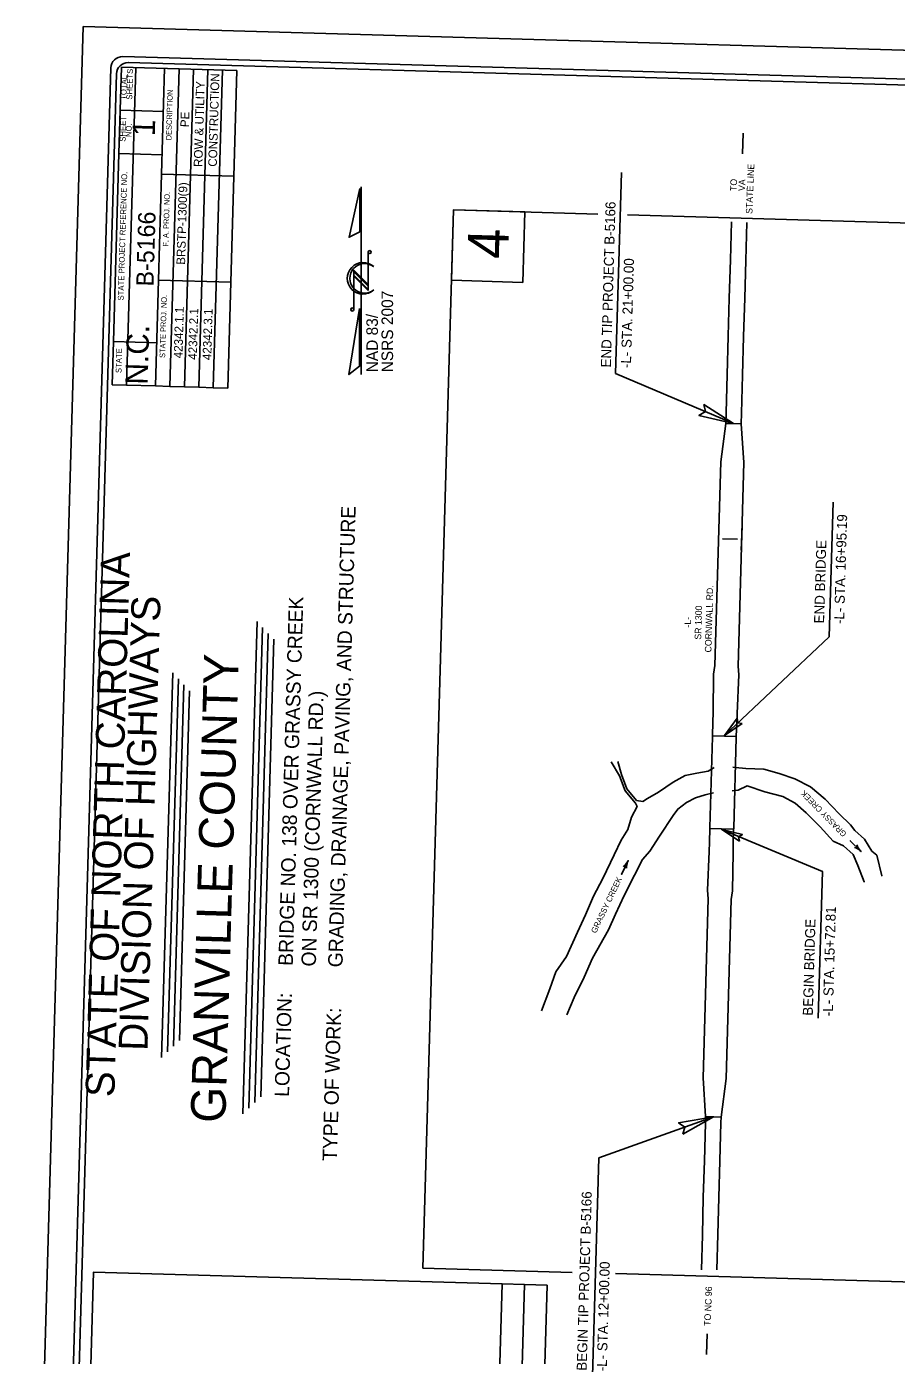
# Model space of a CAD drawing. Extents: x 2097846 to 2099709, y 989477 to 992073.
# Drawn here: x 2097846 to 2098974, y 990349 to 992073 of the extents above; entities that cross this region are included whole.
import ezdxf

# ---------------------------------------------------------------- set-up
doc = ezdxf.new("R2010")
doc.units = 0
for name, color, linetype in [('Exist Hydro Jurisdictional Stream or Body of Water', 7, 'Continuous'), ('Exist Hydro Jurisdictional Stream or Body of Water Text', 7, 'Continuous'), ('Exist Hydro River Flow Arrow CELL', 7, 'Continuous'), ('Exist Roads EOP', 7, 'Continuous'), ('Exist Roads EOP Leader', 7, 'Continuous'), ('Exist Roads EOP Text', 7, 'Continuous'), ('Prop Horizontal Alignment Station Label', 7, 'Continuous'), ('Prop Paved Shoulder', 7, 'Continuous'), ('Prop Shade Light', 7, 'Continuous'), ('Prop Terminator CELL', 7, 'Continuous'), ('Sheet Data Field CELL', 7, 'Continuous'), ('Sheet North Arrow CELL', 7, 'Continuous'), ('Sheet Title CELL', 7, 'Continuous'), ('Stewart Plot Border Xerox6279 and LJ5000', 7, 'Continuous')]:
    doc.layers.add(name, color=color, linetype=linetype)

msp = doc.modelspace()

# ---------------------------------------------------------------- linework, layer by layer
at = {"layer": 'Exist Hydro Jurisdictional Stream or Body of Water'}
for p, q in [((2098920.4, 991029.9), (2098914.8, 991037.2)), ((2098918.2, 990999), (2098905.9, 991010))]:
    msp.add_line(p, q, dxfattribs=at)
for points in [[(2098604.1, 991119.2), (2098615.1, 991100.8), (2098622.6, 991081.7), (2098635.8, 991065.7), (2098638, 991061.1), (2098630.7, 991047.5)], [(2098612.8, 991119.5), (2098617.5, 991102.7), (2098624.7, 991084.1), (2098637.2, 991069), (2098645.5, 991067.5), (2098651.3, 991071.4)], [(2098651.3, 991071.4), (2098665.8, 991080), (2098684.9, 991092.6), (2098700.2, 991101.3), (2098715.5, 991104.5), (2098730.1, 991107), (2098736.7, 991110.9), (2098738, 991111.9)], [(2098762.1, 991112.2), (2098765.7, 991111.8), (2098779.1, 991110.3), (2098802.3, 991109.6), (2098822.4, 991104.1), (2098842.5, 991097.2), (2098863, 991086.9), (2098882, 991070.7), (2098900.2, 991051.9), (2098914.8, 991037.2)], [(2098761.2, 991081.7), (2098768.9, 991082.4), (2098780.7, 991088.1), (2098803.9, 991080.3)], [(2098803.9, 991080.3), (2098827, 991074.2), (2098843.1, 991065.4), (2098857.2, 991052.8), (2098875.6, 991035), (2098892.2, 991016.3), (2098905.9, 991010)], [(2098546.7, 990790.9), (2098556.3, 990813.5), (2098569.3, 990839.8), (2098580.1, 990864.6), (2098601, 990901), (2098609.9, 990921.7), (2098621, 990945.5), (2098634.4, 990972), (2098645, 990992.5), (2098654.4, 991003.4), (2098667, 991022.8), (2098684.8, 991049.6), (2098690.6, 991057.9), (2098702.1, 991066.4), (2098713.9, 991072.4), (2098726.4, 991076.3), (2098737.1, 991078.9)], [(2098513.7, 990795.9), (2098524.7, 990824.8), (2098532.4, 990846.7), (2098546.5, 990866.6), (2098560.8, 990898), (2098571.1, 990920.8), (2098581.3, 990944.9), (2098593.4, 990967.7), (2098608.4, 990998.5), (2098617.1, 991017.4), (2098625.9, 991031.5), (2098630.7, 991047.5)], [(2098920.4, 991029.9), (2098932.9, 991018.7), (2098942.6, 991003.4), (2098949.1, 990997.9), (2098955.7, 990971.1)], [(2098918.2, 990999), (2098924.3, 990984.8), (2098932.8, 990963.5)], [(2098932.8, 990963.5), (2098932.9, 990962.8)], [(2098955.7, 990971.1), (2098955.8, 990970.9)]]:
    msp.add_lwpolyline(points, dxfattribs=at)
at = {"layer": 'Exist Hydro River Flow Arrow CELL'}
for p, q in [((2098921.6, 991009.8), (2098921.6, 991009.8)), ((2098622.2, 990982.1), (2098622.2, 990982.1))]:
    msp.add_line(p, q, dxfattribs=at)
for points in [[(2098923.2, 991011.4), (2098924, 991009.5), (2098924.9, 991007.7), (2098926, 991005.9), (2098927.3, 991004.2), (2098928.7, 991002.7), (2098914.5, 991016.8), (2098928.7, 991002.7), (2098927.1, 991004.1), (2098925.5, 991005.4), (2098923.7, 991006.5), (2098921.8, 991007.4), (2098920, 991008.2)], [(2098620.1, 990983.1), (2098621.6, 990984.5), (2098623, 990986), (2098624.4, 990987.6), (2098625.5, 990989.3), (2098626.5, 990991.1), (2098617.8, 990973.1), (2098626.5, 990991.1), (2098625.7, 990989.3), (2098625.1, 990987.3), (2098624.6, 990985.2), (2098624.3, 990983.2), (2098624.2, 990981.1)]]:
    msp.add_lwpolyline(points, dxfattribs=at)
at = {"layer": 'Exist Roads EOP'}
for points in [[(2098753.2, 991558.4), (2098753.6, 991572.4), (2098755, 991621.5), (2098756.2, 991671.6), (2098757.6, 991720.8), (2098759.1, 991770.8), (2098760.5, 991819.7)], [(2098772.9, 991557.8), (2098773.4, 991571.6), (2098774.8, 991620.9), (2098776.2, 991671.3), (2098777.6, 991720.8), (2098779.1, 991769.9), (2098780.5, 991819.2)], [(2098721.6, 990460.1), (2098722.7, 990505.1), (2098723.9, 990554.1), (2098725.2, 990601.3), (2098726.6, 990650.1), (2098726.8, 990658.8)], [(2098741.6, 990459.8), (2098742.8, 990505.9), (2098744.1, 990553.8), (2098745.3, 990601.2), (2098746.8, 990651.1), (2098747, 990658.2)]]:
    msp.add_lwpolyline(points, dxfattribs=at)
at = {"layer": 'Exist Roads EOP Leader'}
for points in [[(2098775.7, 991935), (2098774.9, 991908.2)], [(2098728.2, 990350), (2098728.9, 990376.8)]]:
    msp.add_lwpolyline(points, dxfattribs=at)
at = {"layer": 'Prop Horizontal Alignment Station Label'}
for points in [[(2098617.6, 991884.1), (2098610.1, 991623.1), (2098763, 991558.1)], [(2098892.2, 991456.3), (2098887.2, 991281.4), (2098751.3, 991153.5)], [(2098872.9, 990786.7), (2098878.4, 990976.9), (2098747.8, 991031.2)], [(2098580.1, 990321.9), (2098588.3, 990605.2), (2098737.1, 990658.5)]]:
    msp.add_lwpolyline(points, dxfattribs=at)
at = {"layer": 'Prop Paved Shoulder'}
msp.add_line((2098773.2, 991393.7), (2098774.1, 991424.7), dxfattribs=at)
at = {"layer": 'Prop Shade Light'}
for p, q in [((2098753.2, 991558.4), (2098746.5, 991508.6)), ((2098772.9, 991557.8), (2098753.2, 991558.4)), ((2098776.5, 991507.7), (2098772.9, 991557.8)), ((2098746.5, 991508.6), (2098738.9, 991244.3)), ((2098768.9, 991243.4), (2098776.5, 991507.7)), ((2098748.6, 991408.5), (2098768.4, 991407.9)), ((2098738.9, 991244.3), (2098737.2, 991233)), ((2098770, 991232), (2098768.9, 991243.4)), ((2098737.2, 991233), (2098736.7, 991183)), ((2098767.6, 991182.1), (2098770, 991232)), ((2098736.4, 991170.5), (2098735.9, 991152.7)), ((2098736.7, 991183), (2098736.4, 991170.5)), ((2098766.7, 991151.9), (2098767.2, 991169.6)), ((2098767.2, 991169.6), (2098767.6, 991182.1)), ((2098735.9, 991152.7), (2098735.8, 991151.7)), ((2098735.9, 991152.7), (2098766.7, 991151.9)), ((2098766.7, 991151.9), (2098735.9, 991152.7)), ((2098763.3, 991032.9), (2098766.7, 991150.9)), ((2098766.7, 991150.9), (2098766.7, 991151.9)), ((2098732.4, 991032.8), (2098731.9, 991015.1)), ((2098763.2, 991031.9), (2098732.4, 991032.8)), ((2098732.4, 991032.8), (2098763.2, 991031.9)), ((2098762.7, 991014.2), (2098763.2, 991031.9)), ((2098763.2, 991031.9), (2098763.3, 991032.9)), ((2098731.9, 991015.1), (2098731.5, 991002.6)), ((2098762.4, 991001.7), (2098762.7, 991014.2)), ((2098731.5, 991002.6), (2098729.1, 990952.6)), ((2098761.9, 990951.7), (2098762.4, 991001.7)), ((2098729.1, 990952.6), (2098730.2, 990941.2)), ((2098760.2, 990940.4), (2098761.9, 990951.7)), ((2098730.2, 990941.2), (2098723.5, 990708.9)), ((2098753.5, 990708.1), (2098760.2, 990940.4)), ((2098723.5, 990708.9), (2098726.8, 990658.8)), ((2098747, 990658.2), (2098753.5, 990708.1)), ((2098726.8, 990658.8), (2098747, 990658.2))]:
    msp.add_line(p, q, dxfattribs=at)
msp.add_lwpolyline([(2098735.8, 991151.7), (2098732.4, 991033.8), (2098732.4, 991032.8)], dxfattribs=at)
at = {"layer": 'Prop Terminator CELL'}
for points in [[(2098724.6, 991582.9), (2098763, 991558.1), (2098718.2, 991568.5), (2098726.6, 991573.6)], [(2098774.1, 991168.7), (2098751.3, 991153.5), (2098767.7, 991175.7), (2098768.5, 991169.8)], [(2098770.8, 991016.3), (2098747.8, 991031.2), (2098774.7, 991025), (2098769.6, 991021.9)], [(2098697.3, 990636), (2098737.1, 990658.5), (2098691.8, 990650.8), (2098699.9, 990645.2)]]:
    msp.add_lwpolyline(points, close=True, dxfattribs=at)
at = {"layer": 'Sheet North Arrow CELL'}
for p, q in [((2098279.8, 991621.7), (2098279.8, 991865.5)), ((2098289, 991780.6), (2098289, 991730.6)), ((2098289, 991738.4), (2098270.3, 991757)), ((2098270.3, 991757), (2098270.3, 991706.2)), ((2098289, 991736.6), (2098270.3, 991755.2)), ((2098270.3, 991755.2), (2098270.3, 991750.6)), ((2098295.9, 991762), (2098296.1, 991761.8)), ((2098289, 991732), (2098270.3, 991750.6)), ((2098270.3, 991750.6), (2098289, 991732)), ((2098289, 991730.6), (2098270.3, 991749.2)), ((2098289, 991732), (2098289, 991736.6))]:
    msp.add_line(p, q, dxfattribs=at)
for points in [[(2098278.1, 991863.3), (2098264.2, 991800), (2098278.1, 991807.1)], [(2098277.8, 991707.6), (2098264, 991621.7), (2098277.8, 991632.6)]]:
    msp.add_lwpolyline(points, close=True, dxfattribs=at)
for centre in [(2098291, 991780.6), (2098268.4, 991706.1)]:
    msp.add_circle(centre, 1.99, dxfattribs=at)
for centre, radius, start, end in [((2098282.4, 991746.6), 20.5, 47.84, 312.3941), ((2098284.4, 991746.6), 19.2, 53.095, 308.6287)]:
    msp.add_arc(centre, radius, start, end, dxfattribs=at)
at = {"layer": 'Sheet Title CELL'}
for p, q in [((2097968.7, 992020.8), (2097967, 991964.6)), ((2098118.6, 992016.5), (2097968.7, 992020.8)), ((2097975.5, 991608), (2097987.4, 992020.3)), ((2098024.9, 992019.2), (2098020.9, 991881.7)), ((2098031.8, 991606.3), (2098043.6, 992018.7)), ((2098062.4, 992018.1), (2098050.5, 991605.8)), ((2098069.3, 991605.3), (2098081.1, 992017.6)), ((2098099.9, 992017.1), (2098088, 991604.7)), ((2098106.7, 991604.2), (2098118.6, 992016.5)), ((2097967, 991964.6), (2097965.4, 991908.4)), ((2097967, 991964.6), (2098023.3, 991963)), ((2097965.4, 991908.4), (2097958.4, 991664.7)), ((2097965.4, 991908.4), (2098021.6, 991906.8)), ((2098020.9, 991881.7), (2098017, 991744.3)), ((2098020.9, 991881.7), (2098114.6, 991879)), ((2098017, 991744.3), (2098013, 991606.9)), ((2098110.7, 991741.6), (2098017, 991744.3)), ((2097958.4, 991664.7), (2097956.8, 991608.5)), ((2098014.6, 991663.1), (2097958.4, 991664.7)), ((2097956.8, 991608.5), (2097975.5, 991608)), ((2097975.5, 991608), (2098013, 991606.9)), ((2098013, 991606.9), (2098031.8, 991606.3)), ((2098031.8, 991606.3), (2098050.5, 991605.8)), ((2098050.5, 991605.8), (2098069.3, 991605.3)), ((2098069.3, 991605.3), (2098088, 991604.7)), ((2098088, 991604.7), (2098106.7, 991604.2)), ((2098126.3, 990662.6), (2098144.8, 991301.4)), ((2098134.1, 990669.9), (2098152, 991293.6)), ((2098141.8, 990677.2), (2098159.3, 991285.9)), ((2098149.5, 990684.5), (2098166.6, 991278.2)), ((2098021, 990735.7), (2098035.4, 991234.6)), ((2098028.7, 990742.9), (2098042.7, 991226.9)), ((2098036.4, 990750.2), (2098049.9, 991219.1)), ((2098044.2, 990757.5), (2098057.2, 991211.4))]:
    msp.add_line(p, q, dxfattribs=at)
for points in [[(2099514.9, 991989.8), (2097970.6, 992034.3)], [(2097955.1, 992019.7), (2097891.2, 989800.6)], [(2097962.4, 992012), (2097901.1, 989882.9)], [(2099229.8, 991990.5), (2097977.8, 992026.6)], [(2098553.8, 990456.6), (2098360, 990462.2), (2098399.6, 991835.3), (2098586.9, 991829.9)], [(2098625.5, 991828.8), (2099141.7, 991813.9), (2099102.2, 990440.8), (2098610, 990455)]]:
    msp.add_lwpolyline(points, dxfattribs=at)
for points in [[(2098399.6, 991835.3), (2098396.9, 991744), (2098489.5, 991741.3), (2098492.1, 991832.7)], [(2097916, 989882.5), (2097932.5, 990456.9), (2098462.8, 990441.6), (2098446.2, 989867.2)], [(2098446.2, 989867.2), (2098462.8, 990441.6), (2098492, 990440.8), (2098475.4, 989866.4)], [(2098475.4, 989866.4), (2098492, 990440.8), (2098521.2, 990439.9), (2098504.6, 989865.5)]]:
    msp.add_lwpolyline(points, close=True, dxfattribs=at)
for centre in [(2097970, 992019.3), (2097977.3, 992011.6)]:
    msp.add_arc(centre, 15, 88.35, 178.35, dxfattribs=at)
at = {"layer": 'Stewart Plot Border Xerox6279 and LJ5000'}
msp.add_lwpolyline([(2099495, 989476.8), (2099568.5, 992025.8), (2097919.2, 992073.3), (2097845.7, 989524.3)], close=True, dxfattribs=at)

# ---------------------------------------------------------------- texts
at = {"layer": 'Exist Hydro Jurisdictional Stream or Body of Water Text'}
for rotation, p in [(134.4133, (2098910.4, 991026.2)), (64.4627, (2098584.5, 990896))]:
    msp.add_text('GRASSY CREEK', height=7.5, rotation=rotation, dxfattribs=at).set_placement(p)
at = {"layer": 'Exist Roads EOP Text'}
for s, rotation, p in [('STATE LINE', 87.7042, (2098787.5, 991830.1)), ('TO', 87.7042, (2098767.1, 991859.8)), ('VA', 87.7042, (2098777.9, 991859.8)), ('CORNWALL RD.', 88.35, (2098734.3, 991261)), ('SR 1300', 88.35, (2098721, 991277.6)), ('TO NC 96', 87.7042, (2098733.3, 990387.1))]:
    msp.add_text(s, height=8.5, rotation=rotation, dxfattribs=at).set_placement(p)
at = {"layer": 'Prop Horizontal Alignment Station Label'}
for s, height, rotation, p in [('END TIP PROJECT B-5166', 13, 88.3496, (2098603.9, 991630.7)), ('-L- STA. 21+00.00', 13, 88.3496, (2098629.9, 991630)), ('-L- STA. 16+95.19', 13, 88.3496, (2098906.5, 991297.8)), ('END BRIDGE', 13, 88.3496, (2098880.5, 991298.6)), ('-L-', 8.5, 88.35, (2098707.7, 991293.3)), ('-L- STA. 15+72.81', 13, 88.3496, (2098891.9, 990788.9)), ('BEGIN BRIDGE', 13, 88.3496, (2098865.9, 990789.6)), ('BEGIN TIP PROJECT B-5166', 13, 88.3496, (2098572.5, 990328.9)), ('-L- STA. 12+00.00', 13, 88.3496, (2098598.5, 990328.1))]:
    msp.add_text(s, height=height, rotation=rotation, dxfattribs=at).set_placement(p)
at = {"layer": 'Sheet Data Field CELL'}
for s, height, rotation, p in [('CONSTRUCTION', 11.25, 88.35, (2098092.6, 991891.3)), ('ROW & UTILITY', 11.25, 88.35, (2098073.8, 991891)), ('PE', 11.25, 88.35, (2098056.5, 991942.6)), ('BRSTP-1300(9)', 11.25, 88.35, (2098051.4, 991764.1)), ('B-5166', 22.5, 88.35, (2098010.4, 991735.9)), ('4', 52.7, 88.35, (2098470.4, 991771.3)), ('42342.1.1', 11.25, 88.35, (2098047.9, 991642.7)), ('42342.2.1', 11.25, 88.35, (2098066.6, 991640.8)), ('42342.3.1', 11.25, 88.35, (2098085.3, 991640.3)), ('GRADING, DRAINAGE, PAVING, AND STRUCTURE', 18.75, 88.35, (2098255.6, 990852.3)), ('BRIDGE NO. 138 OVER GRASSY CREEK', 18.75, 88.3501, (2098191.1, 990854.2)), ('GRANVILLE COUNTY', 45, 88.35, (2098103.6, 990650.2)), ('ON SR 1300 (CORNWALL RD.)', 18.75, 88.3501, (2098221, 990853.3))]:
    msp.add_text(s, height=height, rotation=rotation, dxfattribs=at).set_placement(p)
at = {"layer": 'Sheet North Arrow CELL'}
for s, p in [('NSRS 2007', (2098321.3, 991624.6)), ('NAD 83/', (2098301.6, 991624.6))]:
    msp.add_text(s, height=15, rotation=90, dxfattribs=at).set_placement(p)
at = {"layer": 'Sheet Title CELL'}
for s, height, p in [('SHEETS', 7.5, (2097982.7, 991978.4)), ('TOTAL', 7.5, (2097975.2, 991978.1)), ('DESCRIPTION', 7.2, (2098033.7, 991925.7)), ('SHEET', 7.5, (2097974.1, 991923.8)), ('NO.', 7.5, (2097981.7, 991929.8)), ('1', 29, (2098012.1, 991930.8)), ('STATE PROJECT REFERENCE NO.', 7.5, (2097971.6, 991717.8)), ('F. A. PROJ. NO.', 7.2, (2098029.7, 991787.6)), ('STATE PROJ. NO.', 7.2, (2098025.5, 991643.2)), ('N.C.', 29.03, (2098002.8, 991608.3)), ('STATE', 7.5, (2097968.8, 991623.5)), ('STATE OF NORTH CAROLINA', 37.5, (2097959.6, 990683.7)), ('DIVISION OF HIGHWAYS', 37.5, (2098002.6, 990743.8)), ('LOCATION:', 18.75, (2098186.2, 990684.2)), ('TYPE OF WORK:', 18.75, (2098248.4, 990600.9))]:
    msp.add_text(s, height=height, rotation=88.35, dxfattribs=at).set_placement(p)

doc.saveas('drawing.dxf')
